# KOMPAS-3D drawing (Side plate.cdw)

Views: View 1, Front, View 3, Isometric YZX
Referenced files in C:\Work\01 К О М П А С\Модели примеры\2009_04_For_Poland_AXAPACK\My sample\: Side plate.a3d, Side plate.m3d, rail2.m3d
Referenced files in D:\Documents and Settings\kashirsky\Рабочий стол\: GRAPHIC_DE.LYT
Referenced files: Side plate.cdw
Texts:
  Side plate
  Drawing Annotation
  Dimension Texts
  Surface Finish
  Leader #1
  Leader #2
  Leader #3
  Shape Deviations and Datum
  Table Header
  Table Cell
  Cut/Section Line
  Direction Arrow
  Modification Symbol
  Brace
  Node point number
  Mark of coordination axis
  VRCB
  Leader Text
  Node point designation
  Mark/Reference designation with leader
  Mark/reference designation on line
  Mark/Reference designation without leader
  System Layer
  System View
  Projection View 2
  Specifications
  Unspecified Surface Finish
  BOM table name
  rail2
Dimensions and other numbers on the sheet: 7; 1970; 1820; 1:1; 1; 567,19; 0; 2; 3; 4; 5; 6; 8; 9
